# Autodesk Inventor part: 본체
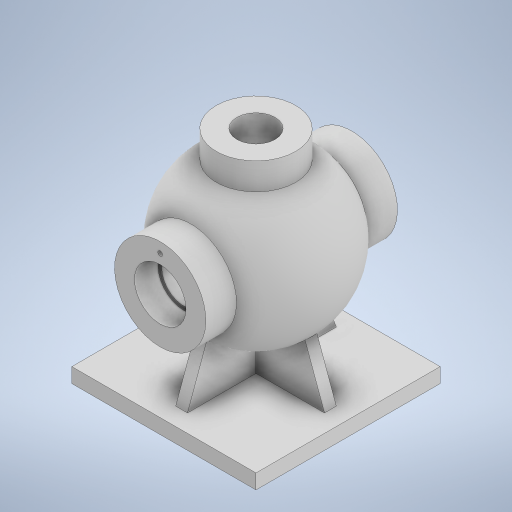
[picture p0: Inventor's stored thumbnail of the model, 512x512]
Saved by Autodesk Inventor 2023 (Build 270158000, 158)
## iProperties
Created: 2023-07
Part Number: 본체
Material: 일반
Document SubType Name: Modeling
Designer: Owner
Density: 1 g/cm^3
Appearance: 기본값
Author: Owner
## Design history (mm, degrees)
sketch "스케치1"
  geometry: L1 (62.5, 62.5)-(-62.5, 62.5); L2 (-62.5, 62.5)-(-62.5, -62.5); L3 (-62.5, -62.5)-(62.5, -62.5); L4 (62.5, -62.5)-(62.5, 62.5); L5 (62.5, 62.5)-(-62.5, -62.5); L6 (-62.5, 62.5)-(62.5, -62.5); 1 further point
  constraints: 12 end point, 2 midpoint, 2 parallel, 1 horizontal, 1 perpendicular
  dimensions: "d0" = 125 distance of L2.end L3.end; "d1" = 125 distance of L1.end L2.end
extrude "돌출1" new body sketch "스케치1" distance "d2" = 10; taper "d3" = 0 deg
sketch "스케치2"
  geometry: L1 (0, -62.5)-(0, 62.5) reference; L2 (85, 65)-(85, -65); L3 (85, 65)-(54, 65); L4 (54, -65)-(85, -65); L5 (54, 65)-(54, 44.215); L6 (54, -44.215)-(54, -65); A1 r 54 centre (85, 0) between (54, 44.215) and (54, -44.215); 2 further points
  constraints: 10 end point, 4 perpendicular, 2 midpoint, 2 point on circle, 1 centre point, 1 horizontal, 1 horizontal alignment, 1 vertical, 1 vertical alignment
  dimensions: "d6" = 130 distance of L2.start L2.end; "d7" = 85 distance between parallel lines of L1 L2; "d8" = 54 radius of A1; "d9" = 31 distance between parallel lines of L6 L2
revolve "회전1" sketch "스케치2" stored, may be unused: angle "d10" = 90 deg
sketch "스케치3"
  geometry: L1 (0, -62.5)-(0, 62.5) reference; L2 (0, 62.5)-(10, 62.5) reference; L3 (10, -62.5)-(10, 62.5) reference; L4 (0, -62.5)-(10, -62.5) reference; L5 (10, 50.5)-(85, 23.202); L6 (85, 23.202)-(85, -23.202); L7 (85, -23.202)-(10, -50.5); 1 further point
  constraints: 6 end point, 2 point on line, 1 vertical
  dimensions: "d11" = 12 distance from line of L4 L7.end; "d12" = 12 distance of L2.end L5.start; "d13" = 20 deg angle of L4 L7; "d14" = 20 deg angle of L2 L5; "d15" = 85 distance between parallel lines of L1 L6
extrude "돌출2" join sketch "스케치3" stored distance "d16" = 8; taper "d17" = 0 deg
sketch "스케치4"
  geometry: L1 (62.5, 10)-(-62.5, 10) reference; L2 (50.5, 10)-(42.822, 31.095); L3 (62.5, 0)-(62.5, 10) reference; 1 further point
  constraints: 2 end point, 1 point on line
  dimensions: "d18" = 12 distance from line of L3 L2.start; "d19" = 20 deg angle of L3 L2
feature "리브1" sketch "스케치4" dims "d20" = 1, "d21" = 8, "d22" = 0, "d23" = 0, "d24" = 1, "d25" = 1
sketch "스케치6"
  geometry: L1 (85, 44)-(85, -44); A1 r 54 centre (85, 0) between (46.034, -37.385) and (46.034, 37.385) reference; A2 r 44 centre (85, 0) between (85, -44) and (85, 44); 2 further points
  constraints: 2 coincident, 2 end point, 2 point on circle, 1 centre point, 1 midpoint, 1 vertical
  dimensions: "d26" = 88 diameter of A2
revolve "회전2" sketch "스케치6" stored, may be unused: angle "d27" = 90 deg
sketch "스케치7"
  geometry: C1 r 31 at (0, 0) reference; 2 further points
  constraints: 1 coincident
hole "구멍1" sketch "스케치7" at (0, 0) diameter "d28" = 30; stored, may be unused: countersink angle "d32" = 90 deg, drill point angle "d34" = 118 deg; dims "d29" = 6, "d30" = 35, "d31" = 16, "d33" = 8
sketch "스케치8"
  geometry: C1 r 31 at (0, 0) reference; 2 further points
  constraints: 1 coincident
hole "구멍2" sketch "스케치8" at (0, 0) diameter "d35" = 30; stored, may be unused: countersink angle "d39" = 90 deg, drill point angle "d41" = 118 deg; dims "d36" = 6, "d37" = 35, "d38" = 16, "d40" = 8
node "작업 평면1"
sketch "스케치9"
  geometry: C1 r 27 at (0, 0); 1 further point
  constraints: 1 centre point, 1 coincident
  dimensions: "d43" = 54 diameter of C1
extrude "돌출3" join sketch "스케치9" stored distance "d44" = 8; taper "d45" = 0 deg
sketch "스케치10"
  geometry: C1 r 27 at (0, 0) reference; 2 further points
  constraints: 1 coincident
hole "구멍3" sketch "스케치10" at (0, 0) diameter "d46" = 26; stored, may be unused: countersink angle "d50" = 90 deg, drill point angle "d52" = 118 deg; dims "d47" = 6, "d48" = 35, "d49" = 16, "d51" = 8
sketch "스케치11"
  geometry: C1 r 17.5 at (0, 0) reference; 2 further points
  constraints: 1 vertical alignment
  dimensions: "d53" = 24 distance of C1.centre point (0, 24)
hole "구멍4" sketch "스케치11" at (0, 24) diameter "d54" = 3.242; stored, may be unused: countersink angle "d58" = 90 deg, drill point angle "d60" = 118 deg; dims "d55" = 12, "d56" = 4, "d57" = 2, "d59" = 15
node "솔리드1"
mirror "미러1"
node "투영된 루프1"
feature "A9D066F2-1C7D-4E18-AEED-F7BC21143FA4" dims "d28" = 30, "d29" = 6, "d30" = 35, "d31" = 16, "d32" = 90 deg, "d33" = 8, "d34" = 118 deg
